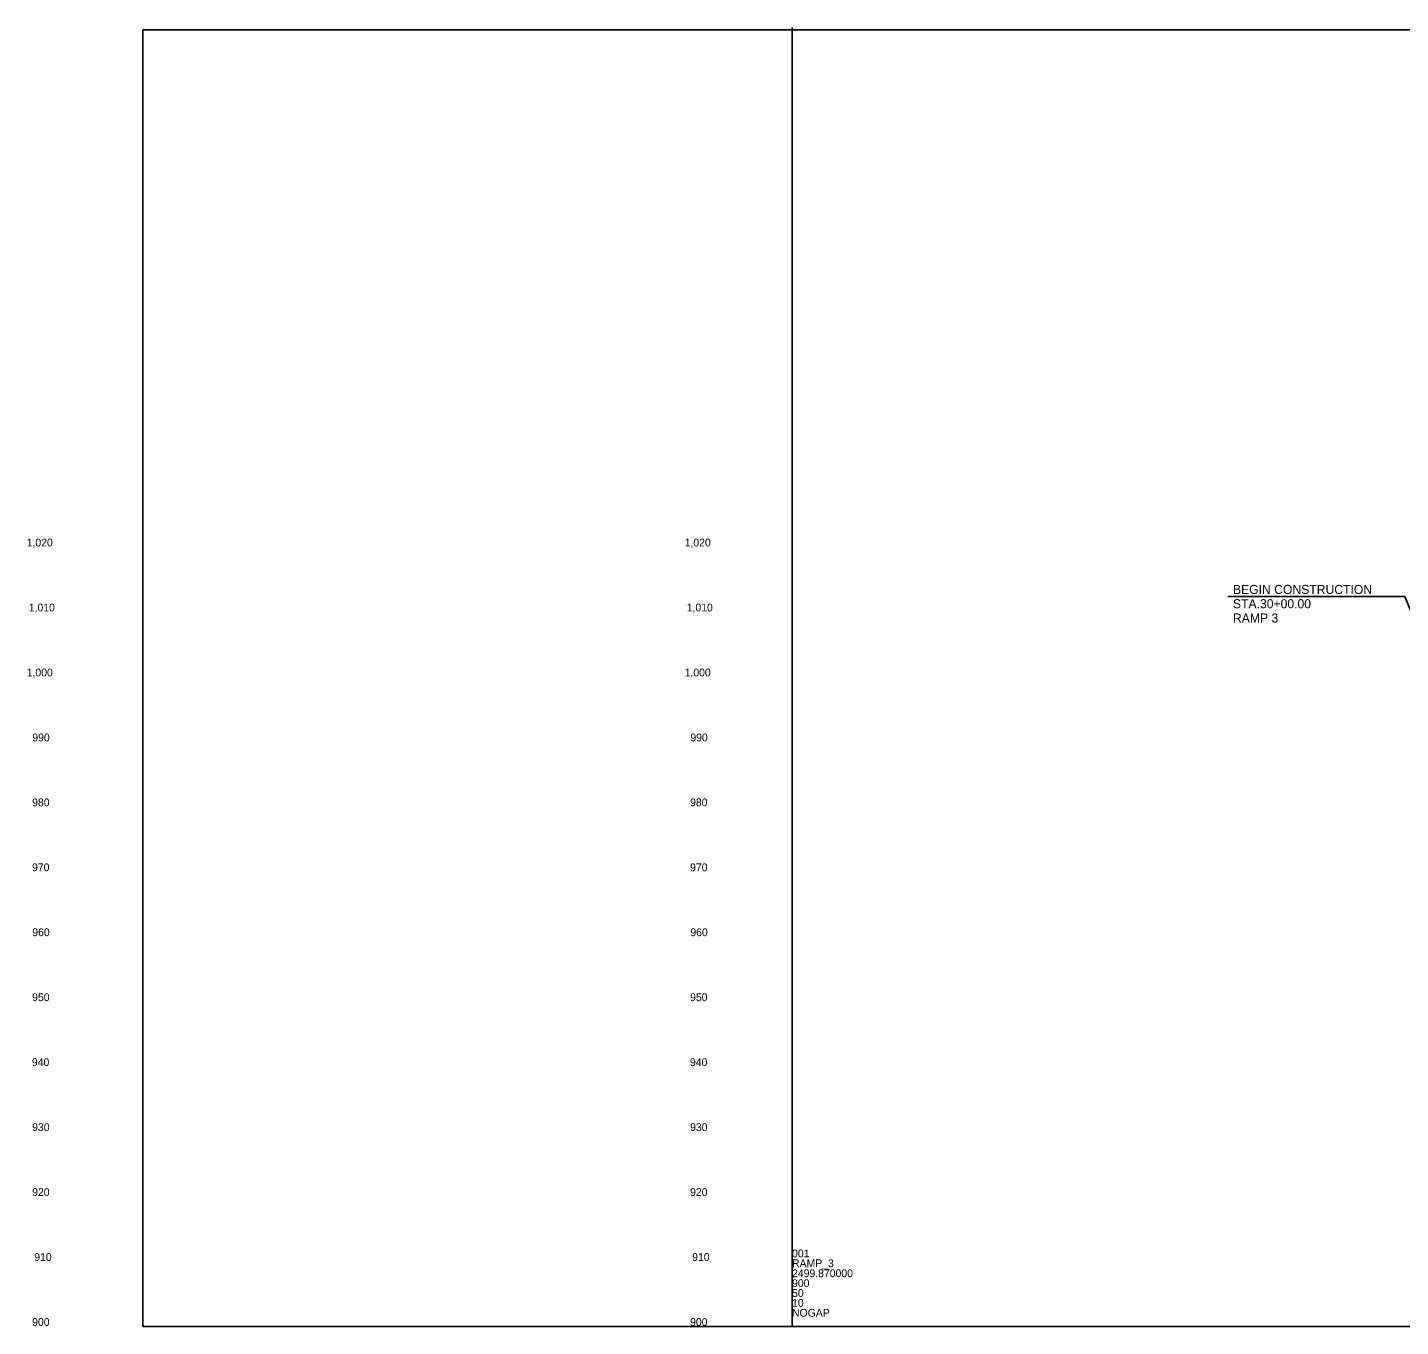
# Model space of a CAD drawing. Extents: x 1150 to 16975538, y 12057 to 12564120.
# Drawn here: x 16972449 to 16973506, y 12563120 to 12564120 of the extents above; entities that cross this region are included whole.
import ezdxf

# ---------------------------------------------------------------- set-up
doc = ezdxf.new("R2010")
doc.units = 0
for name, color, linetype in [('Default', 7, 'Continuous'), ('RD_DDB_ElevTX', 7, 'Continuous'), ('RD_GPK_Profile_Cell', 7, 'Continuous'), ('RD_TX_Utilities', 7, 'Continuous')]:
    doc.layers.add(name, color=color, linetype=linetype)

msp = doc.modelspace()

# ---------------------------------------------------------------- linework, layer by layer
at = {"layer": 'Default'}
msp.add_lwpolyline([(16972537.8, 12563119.9), (16974037.8, 12563119.9), (16974037.8, 12564118.1), (16972537.8, 12564118.1)], close=True, dxfattribs=at)
at = {"layer": 'RD_GPK_Profile_Cell'}
for q in [(16973037.6, 12564119.9), (16975355.1, 12563119.9), (16973037.6, 12563119.9)]:
    msp.add_line((16973037.6, 12563119.9), q, dxfattribs=at)
at = {"layer": 'RD_TX_Utilities'}
msp.add_line((16973503.5, 12563681.8), (16973373, 12563681.8), dxfattribs=at)
msp.add_lwpolyline([(16973503.5, 12563681.8), (16973509.3, 12563681.8), (16973537.8, 12563611.8)], dxfattribs=at)

# ---------------------------------------------------------------- texts
at = {"layer": 'RD_DDB_ElevTX'}
for s, p in [('1,020', (16972448.4, 12563720.4)), ('1,020', (16972954.9, 12563720.4)), ('1,010', (16972450, 12563670.4)), ('1,010', (16972956.5, 12563670.4)), ('1,000', (16972448.4, 12563620.4)), ('1,000', (16972954.9, 12563620.4)), ('990', (16972452.7, 12563570.4)), ('990', (16972959.3, 12563570.4)), ('980', (16972452.6, 12563520.4)), ('980', (16972959.1, 12563520.4)), ('970', (16972452.5, 12563470.4)), ('970', (16972959.1, 12563470.4)), ('960', (16972452.7, 12563420.4)), ('960', (16972959.3, 12563420.4)), ('950', (16972452.6, 12563370.4)), ('950', (16972959.1, 12563370.4)), ('940', (16972452.4, 12563320.4)), ('940', (16972959, 12563320.4)), ('930', (16972452.6, 12563270.4)), ('930', (16972959.1, 12563270.4)), ('920', (16972452.6, 12563220.4)), ('920', (16972959.1, 12563220.4)), ('910', (16972454.2, 12563170.4)), ('910', (16972960.7, 12563170.4)), ('900', (16972452.6, 12563120.4)), ('900', (16972959.1, 12563120.4))]:
    msp.add_text(s, height=6, dxfattribs=at).set_placement(p)
at = {"layer": 'RD_GPK_Profile_Cell'}
for s, p in [('001', (16973037.6, 12563173.2)), ('2499.870000', (16973037.6, 12563157.9)), ('RAMP_3', (16973037.6, 12563165.6)), ('900', (16973037.6, 12563150.3)), ('50', (16973037.6, 12563142.7)), ('10', (16973037.6, 12563135.1)), ('NOGAP', (16973037.6, 12563127.5))]:
    msp.add_text(s, height=6, dxfattribs=at).set_placement(p)
at = {"layer": 'RD_TX_Utilities'}
for s, p in [('BEGIN CONSTRUCTION', (16973377, 12563683.8)), ('STA.30+00.00 ', (16973377, 12563672.8)), ('RAMP 3', (16973377, 12563661.8))]:
    msp.add_text(s, height=7, dxfattribs=at).set_placement(p)

doc.saveas('drawing.dxf')
